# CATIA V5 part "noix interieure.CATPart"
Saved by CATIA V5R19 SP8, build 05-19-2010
Part number: noix interieure
Revision: ANY
Definition: UNKNOWN
Nomenclature: noix interieure
Source: Unknown
Bounding box of the stored display mesh (mm): x -32.608 to 19.701, y -16.861 to 18, z -5.3 to 8.3
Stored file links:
  D:\Documents\1_Travail\1 - ac-limoges.fr\ac-limoges.fr\Emmanuel Maynard - STI2D_Turgot\2 -2I2D\2_SEQUENCE_Serrure_Biométrique\5-Spé_ITEC\Serrure_Bio_Eleve\noix interieure.CATPart
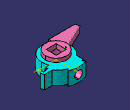
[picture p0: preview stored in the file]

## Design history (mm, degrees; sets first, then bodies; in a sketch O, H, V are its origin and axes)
Set1
  Sketch1 on face of Solid1, origin (0, 0, 1.3), H (1, 0, 0), V (0, 1, 0)
    projected line E1 (-12.3838, -4.504) -> (-32.6082, -13.9349) from edge [face of Solid1 | face of Solid1]
Body1 "Congé3" (main body)
  Solid1: solid without history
